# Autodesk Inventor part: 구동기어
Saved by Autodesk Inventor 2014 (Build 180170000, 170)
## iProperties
Created: 2026-09
Part Number: 구동기어
Material: 일반
Document SubType Name: Modeling
Designer: dg
Density: 1 g/cm^3
Appearance: 기본값
Author: dg
Author: jhkim
Creation Date: 2026-08-26
Sending System: Autodesk Inventor 2027
Preprocessor: ST-DEVELOPER v20.1
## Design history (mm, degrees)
node "구동기어1"
node "솔리드1"
node "기준1"
